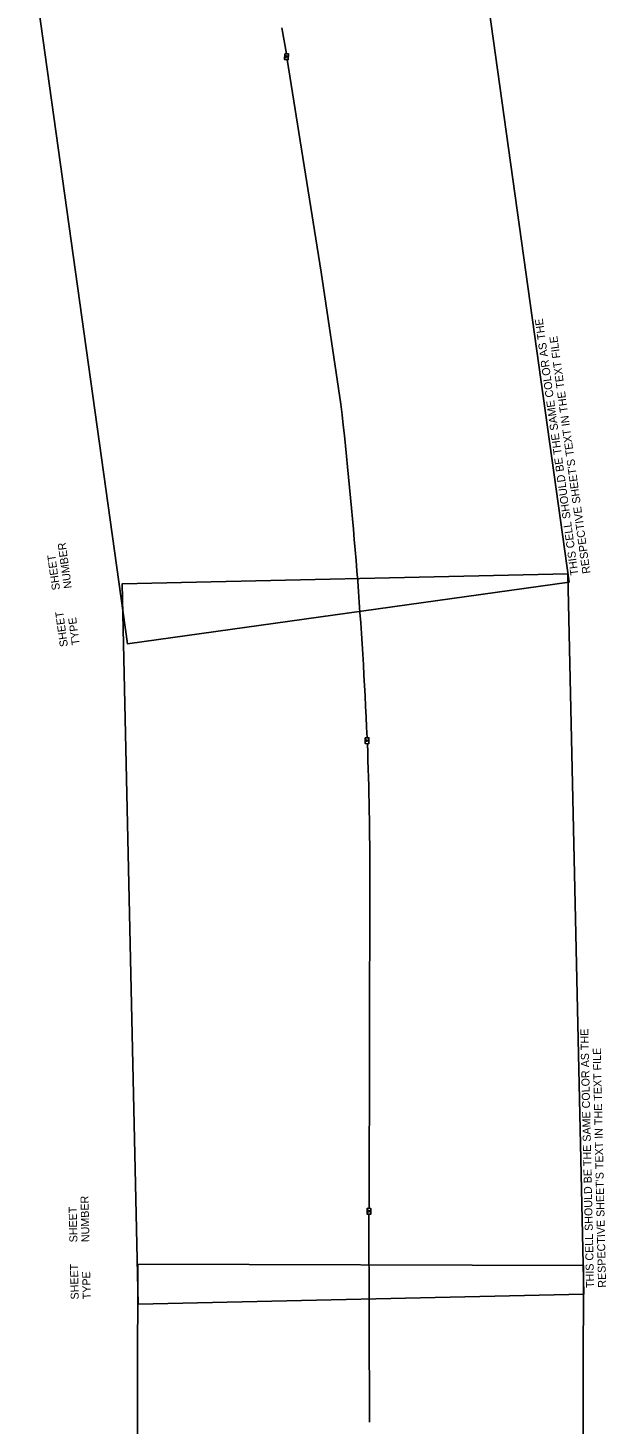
# Model space of a CAD drawing. Extents: x 601462 to 605493, y 331960 to 402715.
# Drawn here: x 602569 to 603834, y 382873 to 385925 of the extents above; entities that cross this region are included whole.
import ezdxf

# ---------------------------------------------------------------- set-up
doc = ezdxf.new("R2010")
doc.units = 0
for name, color, linetype in [('P_FTMS', 7, 'Continuous'), ('P_FTMSConduit', 7, 'Continuous'), ('P_MISC_TXT_1A (Construction)', 7, 'Continuous'), ('P_MISC_TXT_1B (Construction)', 7, 'Continuous')]:
    doc.layers.add(name, color=color, linetype=linetype)

# ---------------------------------------------------------------- blocks, each defined once
blk = doc.blocks.new('FTMS_FCV')
at = {"layer": 'P_FTMS'}
blk.add_line((13, 16), (1, -22), dxfattribs=at)
blk.add_lwpolyline([(39, 24), (-39, 24), (-39, -24), (39, -24)], close=True, dxfattribs=at)
blk.add_lwpolyline([(-12, 16), (1, -22)], dxfattribs=at)

msp = doc.modelspace()

# ---------------------------------------------------------------- linework, layer by layer
at = {"layer": 'P_FTMSConduit'}
for points in [[(603135, 385868.6), (603125, 385925)], [(603254, 385102.1), (603211, 385390.8), (603136.1, 385855.8)], [(603315.4, 383344.3), (603317.2, 384064.9)], [(603316.2, 382876.5), (603315.2, 383331.5)]]:
    msp.add_lwpolyline(points, dxfattribs=at)
for centre, radius, start, end in [((592540.1, 383894.8), 10781.8, 2.54238, 6.42953), ((595536.1, 384071.4), 7781.1, 359.95199, 2.12666)]:
    msp.add_arc(centre, radius, start, end, dxfattribs=at)
at = {"layer": 'P_MISC_TXT_1A (Construction)'}
for points in [[(603753.1, 384713.4), (603535, 386273.2), (602569.4, 386138.2), (602787.5, 384578.3)], [(603753.1, 384713.4), (603535, 386273.2), (602569.4, 386138.2), (602787.5, 384578.3)], [(603780.4, 381644.6), (603784.5, 383219.6), (602809.5, 383222.1), (602805.4, 381647.1)], [(603780.4, 381644.6), (603784.5, 383219.6), (602809.5, 383222.1), (602805.4, 381647.1)]]:
    msp.add_lwpolyline(points, close=True, dxfattribs=at)
at = {"layer": 'P_MISC_TXT_1B (Construction)'}
msp.add_lwpolyline([(603785.4, 383156.9), (603750.1, 384731.5), (602775.4, 384709.6), (602810.7, 383135)], close=True, dxfattribs=at)
msp.add_lwpolyline([(603785.4, 383156.9), (603750.1, 384731.5), (602775.4, 384709.6), (602810.7, 383135)], close=True, dxfattribs=at)

# ---------------------------------------------------------------- block references
at = {"layer": 'P_FTMS', "xscale": 0.16404166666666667, "yscale": 0.16404166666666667, "rotation": 88.76248754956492}
for p in [(603134.9, 385862.2), (603311.1, 384366.6), (603315.3, 383337.9)]:
    msp.add_blockref('FTMS_FCV', p, dxfattribs=at)

# ---------------------------------------------------------------- texts
at = {"layer": 'P_MISC_TXT_1A (Construction)'}
for s, p in [('THIS CELL SHOULD BE THE SAME COLOR AS THE', (603773.7, 384729.3)), ('THIS CELL SHOULD BE THE SAME COLOR AS THE', (603773.7, 384729.3)), ("RESPECTIVE SHEET'S TEXT IN THE TEXT FILE", (603799.7, 384733)), ("RESPECTIVE SHEET'S TEXT IN THE TEXT FILE", (603799.7, 384733)), ('NUMBER', (602665.7, 384700.6)), ('NUMBER', (602665.7, 384700.6)), ('SHEET', (602639.7, 384697)), ('SHEET', (602639.7, 384697)), ('SHEET', (602657, 384573.2)), ('SHEET', (602657, 384573.2)), ('TYPE', (602683, 384576.8)), ('TYPE', (602683, 384576.8))]:
    msp.add_text(s, height=17.5, rotation=97.9598, dxfattribs=at).set_placement(p)
at = {"layer": 'P_MISC_TXT_1B (Construction)'}
for s, p in [('THIS CELL SHOULD BE THE SAME COLOR AS THE', (603807.7, 383170.3)), ('THIS CELL SHOULD BE THE SAME COLOR AS THE', (603807.7, 383170.3)), ("RESPECTIVE SHEET'S TEXT IN THE TEXT FILE", (603834, 383170.9)), ("RESPECTIVE SHEET'S TEXT IN THE TEXT FILE", (603834, 383170.9)), ('NUMBER', (602704, 383270.6)), ('NUMBER', (602704, 383270.6)), ('SHEET', (602677.7, 383270)), ('SHEET', (602677.7, 383270)), ('SHEET', (602680.5, 383145.1)), ('SHEET', (602680.5, 383145.1)), ('TYPE', (602706.8, 383145.6)), ('TYPE', (602706.8, 383145.6))]:
    msp.add_text(s, height=17.5, rotation=91.2836, dxfattribs=at).set_placement(p)

doc.saveas('drawing.dxf')
